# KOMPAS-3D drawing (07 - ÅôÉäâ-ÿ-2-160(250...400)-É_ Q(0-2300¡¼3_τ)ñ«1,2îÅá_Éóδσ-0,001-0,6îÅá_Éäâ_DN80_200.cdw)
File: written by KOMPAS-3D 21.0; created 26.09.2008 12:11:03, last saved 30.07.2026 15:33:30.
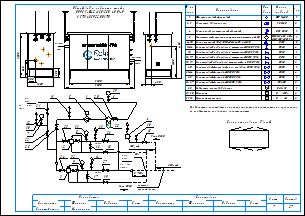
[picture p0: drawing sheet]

Sheets 1-2: A3, landscape

Document properties: Наименование: Макро:21; Автор: RaskoAdmin; Форматы листов документа: 2xA3; Полное имя файла: \\ur38nt01\Departments\КТО\КБ ПУРДГ\Заявки\Прайс-лист на типовые шкафы ГРПШ\ПУРДГ_стандарт_30_04_2026\ПУРДГ с РДГ(Н, В)\ПУРДГ-Ш-2-160(250...400)-Р_ Q(0-2300нм3_ч)до1,2МПа_Рвых-0,001-0,6МПа_РДГ_DN80_200.cdw

Title block, sheet 1: Наименование: Пункт учета газа / ПУГ-Ш-400-Р / ЛГТИ.485922.001ТУ; designation: ЛГТИ.03.4411141; sheet number: 1; Количество листов документа: 2; organisation: ООО "ЭЛЬСТЕР Газэлектроника"; Форматы листов документа: A3; stored path: C:\Рабочие документы\Компас\ПУГ\Схема.cdw; Разработал: Устинов; Проверил: Кошкин; Утвердил: Кошкин
Title block, sheet 2: sheet number: 2; stored path: D:\Рабочие документы\Заявки\ПУРДГ\ПУРДГ-ШУЭО-2-100-Р 4411220.cdw; designation, second copy: ЛГТИ.03.4411141-

Views: Вид 1, Вид 2
Referenced files: wcvoit.frw
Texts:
  Normal
  № на
  схеме
  Усл.
  обозн.
  Марка
  (модель)
  Кол.
  Фильтр газовый фланцевый
  ФГ 16-80
  Регулятор давления газа
  РДГ-50
  Клапан предохранительный сбросной
  ПСК DN25
  Измерительный комплекс с ротационным счетчиком Ду50
  СГ-ЭК-Р-(0,2...2,0)-
  Кран кнопочный VE-РАСКО-НЗ-1,6-G1/2-М20
  DN15
  Кран шаровой "под приварку" штуцерный DN20 PN16
  Кран шаровой "под приварку" штуцерный DN25 PN16
  DN20
  DN25
  Кран шаровой "под приварку" штуцерный DN15 PN16
  Кран шаровой "под приварку" штуцерный п/п DN20 PN16
  Кран шаровой фланцевый с мех. приводом DN80 PN16
  Кран шаровой фланцевый DN50 PN16
  Кран шаровой фланцевый DN80 PN16
  Кран шаровой фланцевый DN200 PN16
  DN80
  DN50
  DN200
  Индикатор перепада давления
  Манометр
  Манометр-напоромер
  Delta 15
  0...     МПа
  0...     кПа
  Общий вид и габариты шкафа
  ПУРДГ-Ш-2-160(250...400)-Р
  Выход газа
  Вход газа
  logo-rasko-ge.png
  DN 1
  местное
  сопротивление
  Римп DN20
  Выход
  газа
  Р=     кПа
  Вход
  Р=       МПа
  PDI
  Схема открывания дверей
  Предприятие изготовитель может заменять комплектующие на аналогичные,
  не ухудшающие заявленных характеристик.
  Должность
  Конструктор
  Фамилия
  Подпись
  Дата
  Согласовано
  Максимкин
  Лист
  Листов
  POLYLINE_STYLE_0.18_RGB_0_0_0
  POLYLINE_STYLE_0.50_RGB_0_0_0
  POLYLINE_STYLE_0.34_RGB_0_0_0
  PHANTOM_RGB_0_0_0_SC_1_THICK_0.18
  K5LT_THIN_RGB_0_0_0_THICK_0.18
  K5LT32769_RGB_0_0_0_THICK_0.18
  K5LT12_RGB_0_0_0_SC_1_THICK_0.18
  K5LT_DASHED_RGB_0_0_0_SC_1_THICK_0.18
  ACISOTGL_RGB_0_0_0_SC_0.8_THICK_0.25
  CONTINUOUS_RGB_0_127_31_THICK_0.3
  CONTINUOUS_RGB_0_0_255_THICK_0.35
  CONTINUOUS_RGB_255_0_0_THICK_0.35
  POLYLINE_STYLE_0.25_RGB_0_0_0
  CONTINUOUS_RGB_0_0_0_THICK_0.5
  POLYLINE_STYLE_0.35_RGB_0_0_255
  CONTINUOUS_RGB_0_0_0_THICK_0.4
  CONTINUOUS_RGB_0_0_0_THICK_0.35
  НЕВИДИМАЯ_RGB_0_0_0_SC_0.3_THICK_0.25
  СONTINUOUS_RGB_0_0_0_THICK_0.25
  ОСЕВАЯ2_RGB_248_153_30_SC_0.3_THICK_0.25
  Без оформления
Dimensions and other numbers on the sheet: 1; 2, 3; 2; 4; 5; -160 (250; 400)/1,6; 6-10; 11-14; 15; 16, 17; 18, 19; 20; 21-24; 25; 26, 27; 28; 29, 30; 31, 32; 1500; 450; 500; 1200; 550; 305; 3300; 4130; 2000; 3600; 5,,,7DN 1; 7; 30; 12; 21; 22; 11; 6; 29; 23; 31; 8; 13; 26; 18; 10; 24; 32; 9; 3; 14; 27; 19; 16; 17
